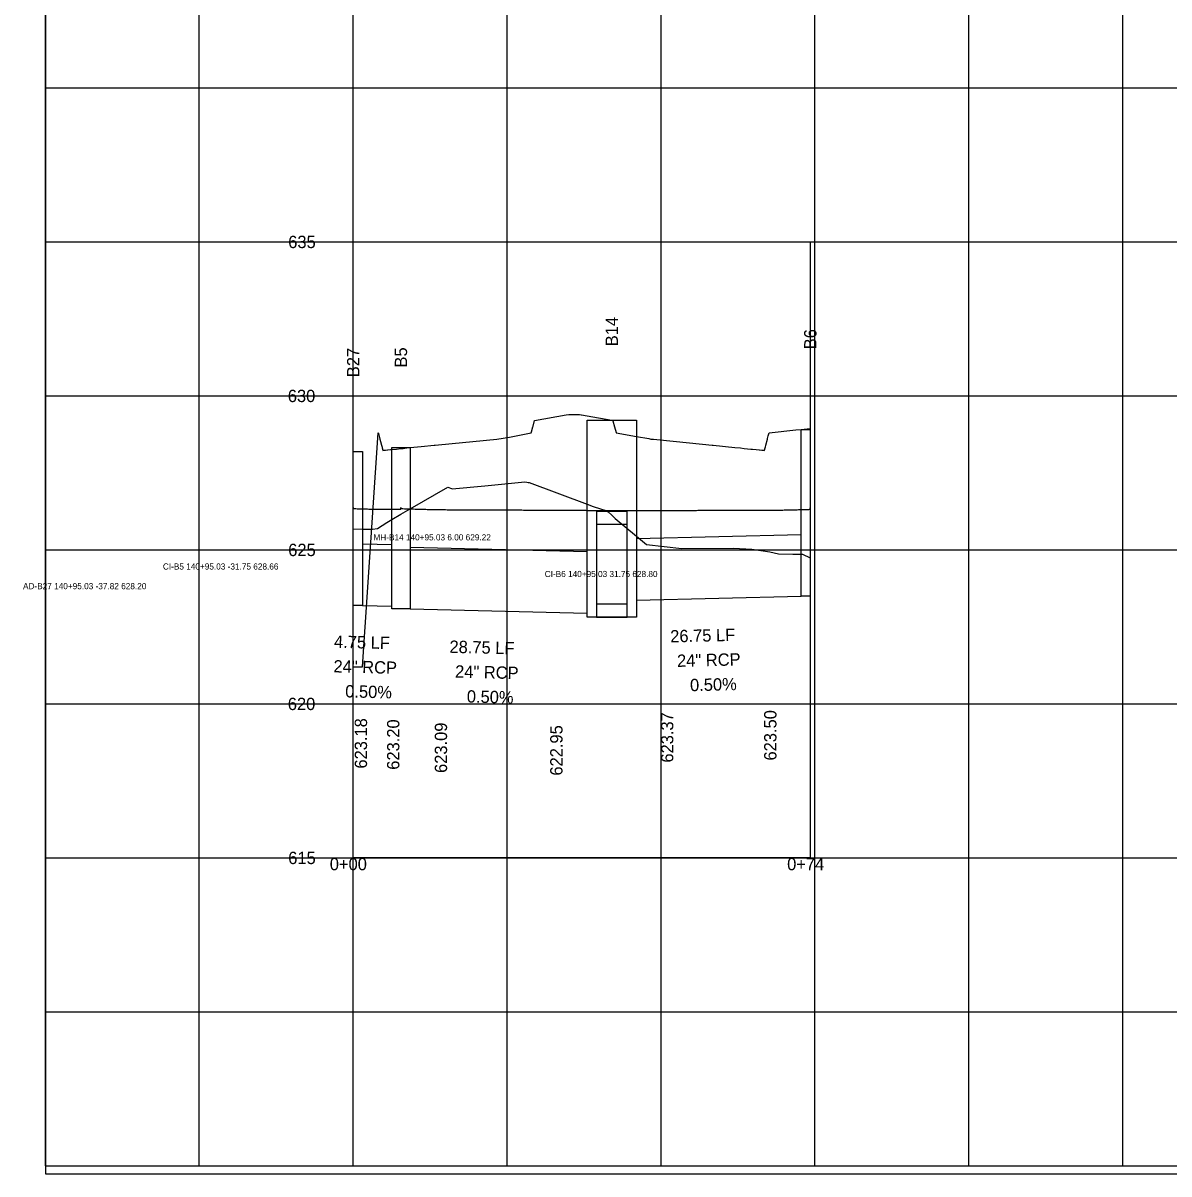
# Model space of a CAD drawing. Extents: x 2253035 to 2279930, y 13774972 to 13793443.
# Drawn here: x 2276745.8 to 2276931.9, y 13792491.3 to 13792678.1 of the extents above; entities that cross this region are included whole.
import ezdxf

# ---------------------------------------------------------------- set-up
doc = ezdxf.new("R2010")
doc.units = 0
for name, color, linetype in [('Default', 7, 'Continuous'), ('E_Utility_ATT_HH', 7, 'Continuous'), ('E_Utility_ATT_PR_PVC', 7, 'Continuous'), ('E_Utility_Telephone_Manhole Telephone_MHT_point', 7, 'Continuous'), ('E_Utility_Telephone_Telephone Pedestal_TPED_Description', 7, 'Continuous'), ('E_Utility_Water_Water Meter_WM_Description', 7, 'Continuous'), ('E_Utillity_Water_Water Line_12in', 7, 'Continuous'), ('E_Utillity_Water_Water Line_1in', 7, 'Continuous'), ('E_Utillity_Water_Water Line_4in', 7, 'Continuous'), ('E_Utillity_Water_Water Line_8in', 7, 'Continuous')]:
    doc.layers.add(name, color=color, linetype=linetype)

msp = doc.modelspace()

# ---------------------------------------------------------------- linework, layer by layer
at = {"layer": 'Default'}
for p, q in [((2276799.4, 13792617.58), (2276873.65, 13792617.58)), ((2276799.4, 13792592.58), (2276873.65, 13792592.58)), ((2276799.4, 13792567.58), (2276873.65, 13792567.58))]:
    msp.add_line(p, q, dxfattribs=at)
msp.add_lwpolyline([(2276799.4, 13792542.58), (2276799.4, 13792642.58), (2276873.65, 13792642.58), (2276873.65, 13792542.58)], close=True, dxfattribs=at)
at = {"layer": 'E_Utility_ATT_PR_PVC'}
for p, q in [((2276807.15, 13792599.2), (2276807.15, 13792599.48)), ((2276841.4, 13792598.99), (2276841.4, 13792598.99))]:
    msp.add_line(p, q, dxfattribs=at)
for points in [[(2276799.4, 13792599.45), (2276799.4, 13792599.28), (2276799.41, 13792599.29), (2276799.62, 13792599.28), (2276799.83, 13792599.28), (2276800.04, 13792599.27), (2276800.24, 13792599.27), (2276800.45, 13792599.26), (2276800.66, 13792599.25), (2276800.87, 13792599.25), (2276801.08, 13792599.24), (2276801.29, 13792599.24), (2276801.5, 13792599.23), (2276801.71, 13792599.23), (2276801.92, 13792599.22), (2276802.13, 13792599.22), (2276802.34, 13792599.21), (2276802.55, 13792599.21), (2276802.76, 13792599.21), (2276802.97, 13792599.21), (2276803.18, 13792599.21), (2276803.39, 13792599.21), (2276803.59, 13792599.21), (2276803.8, 13792599.21), (2276804.01, 13792599.21), (2276804.22, 13792599.21), (2276804.43, 13792599.21), (2276804.64, 13792599.21), (2276804.85, 13792599.21), (2276805.06, 13792599.21), (2276805.27, 13792599.21), (2276805.48, 13792599.21), (2276805.69, 13792599.21), (2276805.9, 13792599.21), (2276806.11, 13792599.2), (2276806.32, 13792599.2), (2276806.53, 13792599.2), (2276806.74, 13792599.2), (2276806.95, 13792599.2), (2276807.15, 13792599.2)], [(2276807.15, 13792599.48), (2276807.15, 13792599.28), (2276807.22, 13792599.29), (2276807.47, 13792599.28), (2276807.72, 13792599.27), (2276807.97, 13792599.26), (2276808.21, 13792599.26), (2276808.46, 13792599.25), (2276808.71, 13792599.24), (2276808.96, 13792599.23), (2276809.21, 13792599.23), (2276809.45, 13792599.22), (2276809.7, 13792599.21), (2276809.95, 13792599.2), (2276810.2, 13792599.2), (2276810.44, 13792599.19), (2276810.69, 13792599.18), (2276810.94, 13792599.17), (2276811.19, 13792599.17), (2276811.43, 13792599.16), (2276811.68, 13792599.15), (2276811.93, 13792599.15), (2276812.18, 13792599.14), (2276812.43, 13792599.13), (2276812.67, 13792599.12), (2276812.92, 13792599.12), (2276813.17, 13792599.12), (2276813.42, 13792599.12), (2276813.66, 13792599.12), (2276813.91, 13792599.12), (2276814.16, 13792599.12), (2276814.41, 13792599.12), (2276814.65, 13792599.11), (2276814.9, 13792599.11), (2276815.15, 13792599.11), (2276815.4, 13792599.11), (2276815.65, 13792599.11), (2276815.89, 13792599.11), (2276816.14, 13792599.11), (2276816.39, 13792599.11), (2276816.64, 13792599.1), (2276816.88, 13792599.1), (2276817.13, 13792599.1), (2276817.38, 13792599.1), (2276817.63, 13792599.1), (2276817.87, 13792599.1), (2276818.12, 13792599.1), (2276818.37, 13792599.1), (2276818.62, 13792599.1), (2276818.87, 13792599.09), (2276819.11, 13792599.09), (2276819.36, 13792599.09), (2276819.61, 13792599.09), (2276819.86, 13792599.09), (2276820.1, 13792599.09), (2276820.35, 13792599.09), (2276820.6, 13792599.09), (2276820.85, 13792599.08), (2276821.09, 13792599.08), (2276821.34, 13792599.08), (2276821.59, 13792599.08), (2276821.84, 13792599.08), (2276822.08, 13792599.08), (2276822.33, 13792599.08), (2276822.58, 13792599.08), (2276822.83, 13792599.07), (2276823.08, 13792599.07), (2276823.32, 13792599.07), (2276823.57, 13792599.07), (2276823.82, 13792599.07), (2276824.07, 13792599.07), (2276824.31, 13792599.07), (2276824.56, 13792599.07), (2276824.81, 13792599.07), (2276825.06, 13792599.06), (2276825.3, 13792599.06), (2276825.55, 13792599.06), (2276825.8, 13792599.06), (2276826.05, 13792599.06), (2276826.3, 13792599.06), (2276826.54, 13792599.06), (2276826.79, 13792599.06), (2276827.04, 13792599.05), (2276827.29, 13792599.05), (2276827.53, 13792599.05), (2276827.78, 13792599.05), (2276828.03, 13792599.05), (2276828.28, 13792599.05), (2276828.52, 13792599.05), (2276828.77, 13792599.05), (2276829.02, 13792599.05), (2276829.27, 13792599.04), (2276829.52, 13792599.04), (2276829.76, 13792599.04), (2276830.01, 13792599.04), (2276830.26, 13792599.04), (2276830.51, 13792599.04), (2276830.75, 13792599.04), (2276831, 13792599.04), (2276831.25, 13792599.03), (2276831.5, 13792599.03), (2276831.74, 13792599.03), (2276831.99, 13792599.03), (2276832.24, 13792599.03), (2276832.49, 13792599.03), (2276832.74, 13792599.03), (2276832.98, 13792599.03), (2276833.23, 13792599.02), (2276833.48, 13792599.02), (2276833.73, 13792599.02), (2276833.97, 13792599.02), (2276834.22, 13792599.02), (2276834.47, 13792599.02), (2276834.72, 13792599.02), (2276834.96, 13792599.02), (2276835.21, 13792599.02), (2276835.46, 13792599.01), (2276835.71, 13792599.01), (2276835.96, 13792599.01), (2276836.2, 13792599.01), (2276836.45, 13792599.01), (2276836.7, 13792599.01), (2276836.95, 13792599.01), (2276837.19, 13792599.01), (2276837.44, 13792599), (2276837.69, 13792599), (2276837.94, 13792599), (2276838.18, 13792599), (2276838.43, 13792599), (2276838.68, 13792599), (2276838.93, 13792599), (2276839.18, 13792599), (2276839.42, 13792598.99), (2276839.67, 13792598.99), (2276839.92, 13792598.99), (2276840.17, 13792598.99), (2276840.41, 13792598.99), (2276840.66, 13792598.99), (2276840.91, 13792598.99), (2276841.16, 13792598.99), (2276841.4, 13792598.99)], [(2276841.4, 13792598.99), (2276841.62, 13792598.99), (2276841.83, 13792598.99), (2276842.04, 13792598.99), (2276842.25, 13792598.99), (2276842.46, 13792598.99), (2276842.68, 13792598.99), (2276842.89, 13792598.99), (2276843.1, 13792598.99), (2276843.31, 13792598.99), (2276843.52, 13792598.99), (2276843.74, 13792598.99), (2276843.95, 13792598.99), (2276844.16, 13792598.99), (2276844.37, 13792598.99), (2276844.58, 13792598.99), (2276844.8, 13792598.99), (2276845.01, 13792598.99), (2276845.22, 13792598.99), (2276845.43, 13792598.99), (2276845.64, 13792598.99), (2276845.86, 13792598.99), (2276846.07, 13792598.99), (2276846.28, 13792598.99), (2276846.49, 13792598.99), (2276846.7, 13792598.99), (2276846.92, 13792598.99), (2276847.13, 13792598.99), (2276847.34, 13792598.99), (2276847.55, 13792598.99), (2276847.76, 13792598.99), (2276847.98, 13792598.99), (2276848.19, 13792598.99), (2276848.4, 13792599), (2276848.61, 13792599), (2276848.82, 13792599), (2276849.04, 13792599), (2276849.25, 13792599), (2276849.46, 13792599), (2276849.67, 13792599), (2276849.88, 13792599), (2276850.1, 13792599), (2276850.31, 13792599), (2276850.52, 13792599), (2276850.73, 13792599), (2276850.94, 13792599), (2276851.15, 13792599), (2276851.37, 13792599), (2276851.58, 13792599), (2276851.79, 13792599), (2276852, 13792599), (2276852.21, 13792599), (2276852.43, 13792599), (2276852.64, 13792599), (2276852.85, 13792599), (2276853.06, 13792599), (2276853.27, 13792599), (2276853.49, 13792599), (2276853.7, 13792599), (2276853.91, 13792599), (2276854.12, 13792599), (2276854.33, 13792599), (2276854.55, 13792599), (2276854.76, 13792599), (2276854.97, 13792599), (2276855.18, 13792599), (2276855.39, 13792599.01), (2276855.61, 13792599.01), (2276855.82, 13792599.01), (2276856.03, 13792599.01), (2276856.24, 13792599.01), (2276856.45, 13792599.01), (2276856.67, 13792599.01), (2276856.88, 13792599.01), (2276857.09, 13792599.01), (2276857.3, 13792599.01), (2276857.51, 13792599.01), (2276857.73, 13792599.01), (2276857.94, 13792599.01), (2276858.15, 13792599.01), (2276858.36, 13792599.01), (2276858.57, 13792599.01), (2276858.79, 13792599.01), (2276859, 13792599.01), (2276859.21, 13792599.01), (2276859.42, 13792599.01), (2276859.63, 13792599.01), (2276859.85, 13792599.01), (2276860.06, 13792599.01), (2276860.27, 13792599.01), (2276860.48, 13792599.01), (2276860.69, 13792599.01), (2276860.91, 13792599.01), (2276861.12, 13792599.01), (2276861.33, 13792599.01), (2276861.54, 13792599.01), (2276861.75, 13792599.01), (2276861.97, 13792599.01), (2276862.18, 13792599.01), (2276862.39, 13792599.02), (2276862.6, 13792599.02), (2276862.81, 13792599.02), (2276863.03, 13792599.02), (2276863.24, 13792599.02), (2276863.45, 13792599.02), (2276863.66, 13792599.02), (2276863.87, 13792599.02), (2276864.09, 13792599.02), (2276864.3, 13792599.02), (2276864.51, 13792599.02), (2276864.72, 13792599.02), (2276864.93, 13792599.02), (2276865.14, 13792599.02), (2276865.36, 13792599.02), (2276865.57, 13792599.02), (2276865.78, 13792599.02), (2276865.99, 13792599.02), (2276866.2, 13792599.02), (2276866.42, 13792599.02), (2276866.63, 13792599.02), (2276866.84, 13792599.02), (2276867.05, 13792599.02), (2276867.26, 13792599.02), (2276867.48, 13792599.02), (2276867.69, 13792599.02), (2276867.9, 13792599.02), (2276868.11, 13792599.02), (2276868.32, 13792599.03), (2276868.54, 13792599.03), (2276868.75, 13792599.04), (2276868.96, 13792599.04), (2276869.17, 13792599.05), (2276869.38, 13792599.06), (2276869.6, 13792599.06), (2276869.81, 13792599.07), (2276870.02, 13792599.07), (2276870.23, 13792599.08), (2276870.44, 13792599.08), (2276870.66, 13792599.09), (2276870.87, 13792599.09), (2276871.08, 13792599.1), (2276871.29, 13792599.11), (2276871.5, 13792599.11), (2276871.72, 13792599.12), (2276871.93, 13792599.12), (2276872.14, 13792599.13), (2276872.35, 13792599.13), (2276872.56, 13792599.14), (2276872.78, 13792599.15), (2276872.99, 13792599.15), (2276873.2, 13792599.16), (2276873.41, 13792599.16), (2276873.62, 13792599.17), (2276873.65, 13792599.16), (2276873.65, 13792599.42)]]:
    msp.add_lwpolyline(points, dxfattribs=at)
at = {"layer": 'E_Utility_Telephone_Manhole Telephone_MHT_point'}
for p, q in [((2276749.4, 13792492.6), (2276749.4, 13792792.6)), ((2276774.4, 13792492.6), (2276774.4, 13792792.6)), ((2276799.4, 13792492.6), (2276799.4, 13792792.6)), ((2276824.4, 13792492.6), (2276824.4, 13792792.6)), ((2276849.4, 13792492.6), (2276849.4, 13792792.6)), ((2276874.4, 13792492.6), (2276874.4, 13792792.6)), ((2276899.4, 13792492.6), (2276899.4, 13792792.6)), ((2276924.4, 13792492.6), (2276924.4, 13792792.6)), ((2276749.4, 13792667.6), (2277074.4, 13792667.6)), ((2276749.4, 13792642.6), (2277074.4, 13792642.6)), ((2276749.4, 13792617.6), (2277074.4, 13792617.6)), ((2276749.4, 13792592.6), (2277074.4, 13792592.6)), ((2276749.4, 13792567.6), (2277074.4, 13792567.6)), ((2276749.4, 13792542.6), (2277074.4, 13792542.6)), ((2276749.4, 13792517.6), (2277074.4, 13792517.6)), ((2276749.4, 13792492.6), (2277074.4, 13792492.6))]:
    msp.add_line(p, q, dxfattribs=at)
at = {"layer": 'E_Utility_Water_Water Meter_WM_Description'}
msp.add_lwpolyline([(2277133.03, 13792792.44), (2276749.4, 13792792.44), (2276749.4, 13792491.27), (2277133.03, 13792491.27)], close=True, dxfattribs=at)
at = {"layer": 'E_Utillity_Water_Water Line_12in'}
for points in [[(2276837.4, 13792613.62), (2276845.4, 13792613.62), (2276845.4, 13792581.68), (2276837.4, 13792581.68)], [(2276872.15, 13792612.14), (2276873.65, 13792612.14), (2276873.65, 13792585.08), (2276872.15, 13792585.08)], [(2276799.4, 13792608.58), (2276800.9, 13792608.58), (2276800.9, 13792583.58), (2276799.4, 13792583.58)], [(2276805.65, 13792609.18), (2276808.65, 13792609.18), (2276808.65, 13792583.04), (2276805.65, 13792583.04)]]:
    msp.add_lwpolyline(points, close=True, dxfattribs=at)
at = {"layer": 'E_Utillity_Water_Water Line_1in'}
msp.add_lwpolyline([(2276799.4, 13792595.99), (2276800.9, 13792595.97), (2276800.9, 13792595.97), (2276802.53, 13792595.94), (2276803.37, 13792596.03), (2276804.86, 13792597.05), (2276805.65, 13792597.51), (2276805.65, 13792597.51), (2276807.15, 13792598.37), (2276807.15, 13792598.37), (2276808.65, 13792599.23), (2276808.65, 13792599.23), (2276814.79, 13792602.74), (2276815.38, 13792602.53), (2276815.45, 13792602.5), (2276820.77, 13792602.96), (2276827.28, 13792603.62), (2276827.59, 13792603.56), (2276827.81, 13792603.53), (2276827.98, 13792603.53), (2276837.4, 13792600.01), (2276837.4, 13792600.01), (2276838.4, 13792599.64), (2276840.59, 13792598.92), (2276840.84, 13792598.76), (2276841.4, 13792598.22), (2276841.4, 13792598.22), (2276841.98, 13792597.67), (2276845.4, 13792594.82), (2276845.4, 13792594.82), (2276847.02, 13792593.48), (2276852.79, 13792592.8), (2276861.16, 13792592.84), (2276864.14, 13792592.71), (2276867.07, 13792592.25), (2276868.46, 13792591.93), (2276870.79, 13792591.88), (2276872.15, 13792591.91), (2276872.15, 13792591.91), (2276872.36, 13792591.91), (2276873.65, 13792591.3)], dxfattribs=at)
at = {"layer": 'E_Utillity_Water_Water Line_4in'}
for p, q in [((2276845.4, 13792594.41), (2276872.15, 13792595.08)), ((2276800.9, 13792593.58), (2276805.65, 13792593.46)), ((2276808.65, 13792593.04), (2276837.4, 13792592.32)), ((2276800.9, 13792583.58), (2276805.65, 13792583.46)), ((2276845.4, 13792584.41), (2276872.15, 13792585.08)), ((2276808.65, 13792583.04), (2276837.4, 13792582.32))]:
    msp.add_line(p, q, dxfattribs=at)
for points in [[(2276838.9, 13792583.83), (2276843.9, 13792583.83), (2276843.9, 13792598.83), (2276838.9, 13792598.83)], [(2276838.9, 13792581.68), (2276843.9, 13792581.68), (2276843.9, 13792596.68), (2276838.9, 13792596.68)]]:
    msp.add_lwpolyline(points, close=True, dxfattribs=at)
at = {"layer": 'E_Utillity_Water_Water Line_8in'}
msp.add_lwpolyline([(2276799.4, 13792573.58), (2276800.9, 13792573.58), (2276800.9, 13792573.58), (2276803.48, 13792611.58), (2276803.49, 13792611.55), (2276803.51, 13792611.49), (2276803.68, 13792610.82), (2276803.74, 13792610.58), (2276803.84, 13792610.2), (2276804, 13792609.58), (2276804, 13792609.57), (2276804.08, 13792609.26), (2276804.08, 13792609.25), (2276804.1, 13792609.17), (2276804.12, 13792609.13), (2276804.15, 13792608.99), (2276804.16, 13792608.96), (2276804.17, 13792608.9), (2276804.18, 13792608.87), (2276804.19, 13792608.84), (2276804.19, 13792608.82), (2276804.2, 13792608.81), (2276804.2, 13792608.8), (2276804.2, 13792608.78), (2276804.2, 13792608.78), (2276804.21, 13792608.77), (2276804.21, 13792608.76), (2276804.21, 13792608.75), (2276804.21, 13792608.75), (2276804.21, 13792608.75), (2276804.21, 13792608.74), (2276804.22, 13792608.73), (2276804.37, 13792608.75), (2276804.38, 13792608.75), (2276804.62, 13792608.77), (2276804.65, 13792608.78), (2276804.96, 13792608.81), (2276805.02, 13792608.81), (2276805.44, 13792608.86), (2276805.56, 13792608.87), (2276805.65, 13792608.88), (2276805.65, 13792608.88), (2276805.71, 13792608.88), (2276806.45, 13792608.96), (2276807.15, 13792609.03), (2276807.15, 13792609.03), (2276807.51, 13792609.06), (2276808.13, 13792609.13), (2276808.65, 13792609.18), (2276808.65, 13792609.18), (2276810.45, 13792609.36), (2276812.58, 13792609.57), (2276812.71, 13792609.58), (2276813.26, 13792609.64), (2276822.71, 13792610.58), (2276824.77, 13792610.91), (2276825.88, 13792611.12), (2276828.04, 13792611.53), (2276828.33, 13792611.58), (2276828.37, 13792611.74), (2276828.59, 13792612.58), (2276828.61, 13792612.66), (2276828.85, 13792613.58), (2276833.99, 13792614.51), (2276834.44, 13792614.58), (2276835.93, 13792614.58), (2276836.14, 13792614.58), (2276836.45, 13792614.53), (2276836.48, 13792614.52), (2276837.4, 13792614.35), (2276837.4, 13792614.35), (2276841.4, 13792613.62), (2276841.4, 13792613.62), (2276841.59, 13792613.58), (2276841.6, 13792613.53), (2276841.84, 13792612.58), (2276842.09, 13792611.64), (2276842.1, 13792611.58), (2276845.4, 13792611), (2276845.4, 13792611), (2276847.4, 13792610.64), (2276847.44, 13792610.64), (2276847.72, 13792610.58), (2276847.89, 13792610.57), (2276848.17, 13792610.54), (2276851.94, 13792610.16), (2276857.72, 13792609.58), (2276857.86, 13792609.57), (2276861.4, 13792609.22), (2276862.3, 13792609.13), (2276862.92, 13792609.06), (2276863.98, 13792608.96), (2276864.24, 13792608.93), (2276864.87, 13792608.87), (2276865.35, 13792608.82), (2276865.42, 13792608.81), (2276865.75, 13792608.78), (2276865.79, 13792608.78), (2276866.04, 13792608.75), (2276866.05, 13792608.75), (2276866.22, 13792608.73), (2276866.22, 13792608.74), (2276866.22, 13792608.75), (2276866.22, 13792608.75), (2276866.22, 13792608.75), (2276866.22, 13792608.76), (2276866.22, 13792608.76), (2276866.23, 13792608.77), (2276866.23, 13792608.78), (2276866.23, 13792608.79), (2276866.23, 13792608.8), (2276866.23, 13792608.81), (2276866.24, 13792608.81), (2276866.24, 13792608.84), (2276866.25, 13792608.85), (2276866.25, 13792608.87), (2276866.26, 13792608.92), (2276866.27, 13792608.96), (2276866.29, 13792609.04), (2276866.3, 13792609.08), (2276866.32, 13792609.13), (2276866.36, 13792609.3), (2276866.36, 13792609.3), (2276866.42, 13792609.53), (2276866.43, 13792609.57), (2276866.43, 13792609.58), (2276866.69, 13792610.58), (2276866.69, 13792610.58), (2276866.71, 13792610.65), (2276866.83, 13792611.11), (2276866.95, 13792611.58), (2276871.31, 13792612.05), (2276872.15, 13792612.14), (2276872.15, 13792612.14), (2276873.65, 13792612.3)], dxfattribs=at)

# ---------------------------------------------------------------- texts
at = {"layer": 'Default'}
for s, p in [('635', (2276788.85, 13792641.58)), ('630', (2276788.78, 13792616.58)), ('625', (2276788.85, 13792591.58)), ('620', (2276788.78, 13792566.58)), ('615', (2276788.85, 13792541.58)), ('0+00', (2276795.6, 13792540.58)), ('0+74', (2276869.89, 13792540.58))]:
    msp.add_text(s, height=2, dxfattribs=at).set_placement(p)
at = {"layer": 'E_Utility_ATT_HH'}
for s, rotation, p in [('B14', 90, (2276842.4, 13792625.65)), ('B6', 90, (2276874.65, 13792625.15)), ('B27', 90, (2276800.4, 13792620.62)), ('B5', 90, (2276808.15, 13792622.19)), ('26.75 LF', 1.4321, (2276850.92, 13792577.55)), ('4.75 LF', 358.5679, (2276796.27, 13792576.7)), ('28.75 LF', 358.5679, (2276815.02, 13792575.88)), ('24" RCP', 358.5679, (2276796.18, 13792572.7)), ('24" RCP', 1.4321, (2276852.03, 13792573.58)), ('24" RCP', 358.5679, (2276815.93, 13792571.86)), ('0.50%', 358.5679, (2276798.09, 13792568.65)), ('0.50%', 1.4321, (2276854.14, 13792569.63)), ('0.50%', 358.5679, (2276817.84, 13792567.81)), ('623.18', 90, (2276801.65, 13792557.08)), ('623.20', 90, (2276806.9, 13792556.89)), ('623.37', 90, (2276851.4, 13792558.05)), ('623.50', 90, (2276868.15, 13792558.39)), ('623.09', 90, (2276814.65, 13792556.37)), ('622.95', 90, (2276833.4, 13792555.94))]:
    msp.add_text(s, height=2, rotation=rotation, dxfattribs=at).set_placement(p)
at = {"layer": 'E_Utility_Telephone_Telephone Pedestal_TPED_Description'}
for s, p in [('MH-B14 140+95.03 6.00 629.22', (2276802.69, 13792594.12)), ('CI-B5 140+95.03 -31.75 628.66', (2276768.49, 13792589.39)), ('CI-B6 140+95.03 31.75 628.80', (2276830.51, 13792588.17)), ('AD-B27 140+95.03 -37.82 628.20', (2276745.77, 13792586.2))]:
    msp.add_text(s, height=1, rotation=0, dxfattribs=at).set_placement(p)

doc.saveas('drawing.dxf')
